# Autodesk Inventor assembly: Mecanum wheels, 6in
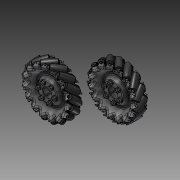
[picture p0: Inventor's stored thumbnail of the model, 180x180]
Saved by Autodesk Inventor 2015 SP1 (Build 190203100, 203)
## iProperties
Created: 2015-02
Part Number: Mecanum wheels, 6in
Document SubType Name: Assembly
Designer: TODD D MILLER
Mass: 1427.07 g
Surface Area: 3105.51 cm^2
Volume: 417.339 cm^3
Density: 3.41946 g/cm^3
Author: TODD D MILLER
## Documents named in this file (3)
- C:\Users\TODD D MILLER\Documents\GrabCAD\ElkLogics FRC\CAD Library\Mecanum wheels\Mecanum wheels, 6in.iam
- C:\Users\TODD D MILLER\Documents\GrabCAD\ElkLogics FRC\CAD Library\Mecanum wheels\6-mecanum-3-Left with HUB.iam
- C:\Users\TODD D MILLER\Documents\GrabCAD\ElkLogics FRC\CAD Library\Mecanum wheels\6-mecanum-3-Right with HUB.iam
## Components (2 placed, 2 different names)
1. 6-mecanum-3-Left with HUB:1 [sub-assembly]
2. 6-mecanum-3-Right with HUB:1 [sub-assembly]
